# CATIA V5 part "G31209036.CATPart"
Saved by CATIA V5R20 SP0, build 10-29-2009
Part number: G31209036
Revision: 7
Definition: design
Nomenclature: G31209036
Source: made
Description: NOT SPECIFIED
Bounding box of the stored display mesh (mm): x -5 to 36, y -8 to 8, z -8 to 8
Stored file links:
  C:\Users\Raffaele\Desktop\3D X SITO CF\BOLEX\23-BUSH REF 312\G31209036.CATPart

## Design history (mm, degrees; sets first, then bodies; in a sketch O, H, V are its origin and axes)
Body1 "MANIFOLD_SOLID_BREP #9695" (main body)
  Solid1: solid without history
Body2 "MANIFOLD_SOLID_BREP #9838"
  Solid2: solid without history
Body3 "MANIFOLD_SOLID_BREP #9981"
  Solid3: solid without history
Body4 "MANIFOLD_SOLID_BREP #10124"
  Solid4: solid without history
Body5 "MANIFOLD_SOLID_BREP #10267"
  Solid5: solid without history
Body6 "MANIFOLD_SOLID_BREP #10410"
  Solid6: solid without history
Body7 "MANIFOLD_SOLID_BREP #10553"
  Solid7: solid without history
Body8 "MANIFOLD_SOLID_BREP #10698"
  Solid8: solid without history
Body9 "MANIFOLD_SOLID_BREP #10843"
  Solid9: solid without history
Body10 "MANIFOLD_SOLID_BREP #10988"
  Solid10: solid without history
Body11 "MANIFOLD_SOLID_BREP #11133"
  Solid11: solid without history
Body12 "MANIFOLD_SOLID_BREP #11276"
  Solid12: solid without history
Body13 "MANIFOLD_SOLID_BREP #11419"
  Solid13: solid without history
Body14 "MANIFOLD_SOLID_BREP #11564"
  Solid14: solid without history
Body15 "MANIFOLD_SOLID_BREP #11709"
  Solid15: solid without history
Body16 "MANIFOLD_SOLID_BREP #11854"
  Solid16: solid without history
Body17 "MANIFOLD_SOLID_BREP #11999"
  Solid17: solid without history
Body18 "MANIFOLD_SOLID_BREP #12144"
  Solid18: solid without history
Body19 "MANIFOLD_SOLID_BREP #12289"
  Solid19: solid without history
Body20 "MANIFOLD_SOLID_BREP #12434"
  Solid20: solid without history
Body21 "MANIFOLD_SOLID_BREP #12579"
  Solid21: solid without history
Body22 "MANIFOLD_SOLID_BREP #12724"
  Solid22: solid without history
Body23 "MANIFOLD_SOLID_BREP #12869"
  Solid23: solid without history
Body24 "MANIFOLD_SOLID_BREP #13014"
  Solid24: solid without history
Body25 "MANIFOLD_SOLID_BREP #13159"
  Solid25: solid without history
Body26 "MANIFOLD_SOLID_BREP #13304"
  Solid26: solid without history
Body27 "MANIFOLD_SOLID_BREP #13449"
  Solid27: solid without history
Body28 "MANIFOLD_SOLID_BREP #13594"
  Solid28: solid without history
Body29 "MANIFOLD_SOLID_BREP #13737"
  Solid29: solid without history
Body30 "MANIFOLD_SOLID_BREP #13882"
  Solid30: solid without history
Body31 "MANIFOLD_SOLID_BREP #14027"
  Solid31: solid without history
Body32 "MANIFOLD_SOLID_BREP #14170"
  Solid32: solid without history
Body33 "MANIFOLD_SOLID_BREP #14315"
  Solid33: solid without history
Body34 "MANIFOLD_SOLID_BREP #14460"
  Solid34: solid without history
Body35 "MANIFOLD_SOLID_BREP #14603"
  Solid35: solid without history
Body36 "MANIFOLD_SOLID_BREP #14746"
  Solid36: solid without history
Body37 "MANIFOLD_SOLID_BREP #14891"
  Solid37: solid without history
Body38 "MANIFOLD_SOLID_BREP #15036"
  Solid38: solid without history
Body39 "MANIFOLD_SOLID_BREP #15181"
  Solid39: solid without history
Body40 "MANIFOLD_SOLID_BREP #15326"
  Solid40: solid without history
Body41 "MANIFOLD_SOLID_BREP #15471"
  Solid41: solid without history
Body42 "MANIFOLD_SOLID_BREP #15616"
  Solid42: solid without history
Body43 "MANIFOLD_SOLID_BREP #15761"
  Solid43: solid without history
Body44 "MANIFOLD_SOLID_BREP #15904"
  Solid44: solid without history
Body45 "MANIFOLD_SOLID_BREP #16049"
  Solid45: solid without history
Body46 "MANIFOLD_SOLID_BREP #16194"
  Solid46: solid without history
Body47 "MANIFOLD_SOLID_BREP #16337"
  Solid47: solid without history
Body48 "MANIFOLD_SOLID_BREP #16482"
  Solid48: solid without history
Body49 "MANIFOLD_SOLID_BREP #16627"
  Solid49: solid without history
Body50 "MANIFOLD_SOLID_BREP #16772"
  Solid50: solid without history
Body51 "MANIFOLD_SOLID_BREP #16917"
  Solid51: solid without history
Body52 "MANIFOLD_SOLID_BREP #17062"
  Solid52: solid without history
Body53 "MANIFOLD_SOLID_BREP #17207"
  Solid53: solid without history
Body54 "MANIFOLD_SOLID_BREP #17352"
  Solid54: solid without history
Body55 "MANIFOLD_SOLID_BREP #17497"
  Solid55: solid without history
Body56 "MANIFOLD_SOLID_BREP #17642"
  Solid56: solid without history
Body57 "MANIFOLD_SOLID_BREP #17785"
  Solid57: solid without history
Body58 "MANIFOLD_SOLID_BREP #17928"
  Solid58: solid without history
Body59 "MANIFOLD_SOLID_BREP #18071"
  Solid59: solid without history
Body60 "MANIFOLD_SOLID_BREP #18216"
  Solid60: solid without history
Body61 "MANIFOLD_SOLID_BREP #18361"
  Solid61: solid without history
Body62 "MANIFOLD_SOLID_BREP #18504"
  Solid62: solid without history
Body63 "MANIFOLD_SOLID_BREP #18649"
  Solid63: solid without history
Body64 "MANIFOLD_SOLID_BREP #18794"
  Solid64: solid without history
Body65 "MANIFOLD_SOLID_BREP #18937"
  Solid65: solid without history
Body66 "MANIFOLD_SOLID_BREP #19080"
  Solid66: solid without history
Body67 "MANIFOLD_SOLID_BREP #19225"
  Solid67: solid without history
Body68 "MANIFOLD_SOLID_BREP #19370"
  Solid68: solid without history
Body69 "MANIFOLD_SOLID_BREP #19515"
  Solid69: solid without history
Body70 "MANIFOLD_SOLID_BREP #19660"
  Solid70: solid without history
Body71 "MANIFOLD_SOLID_BREP #19805"
  Solid71: solid without history
Body72 "MANIFOLD_SOLID_BREP #19950"
  Solid72: solid without history
Body73 "MANIFOLD_SOLID_BREP #20095"
  Solid73: solid without history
